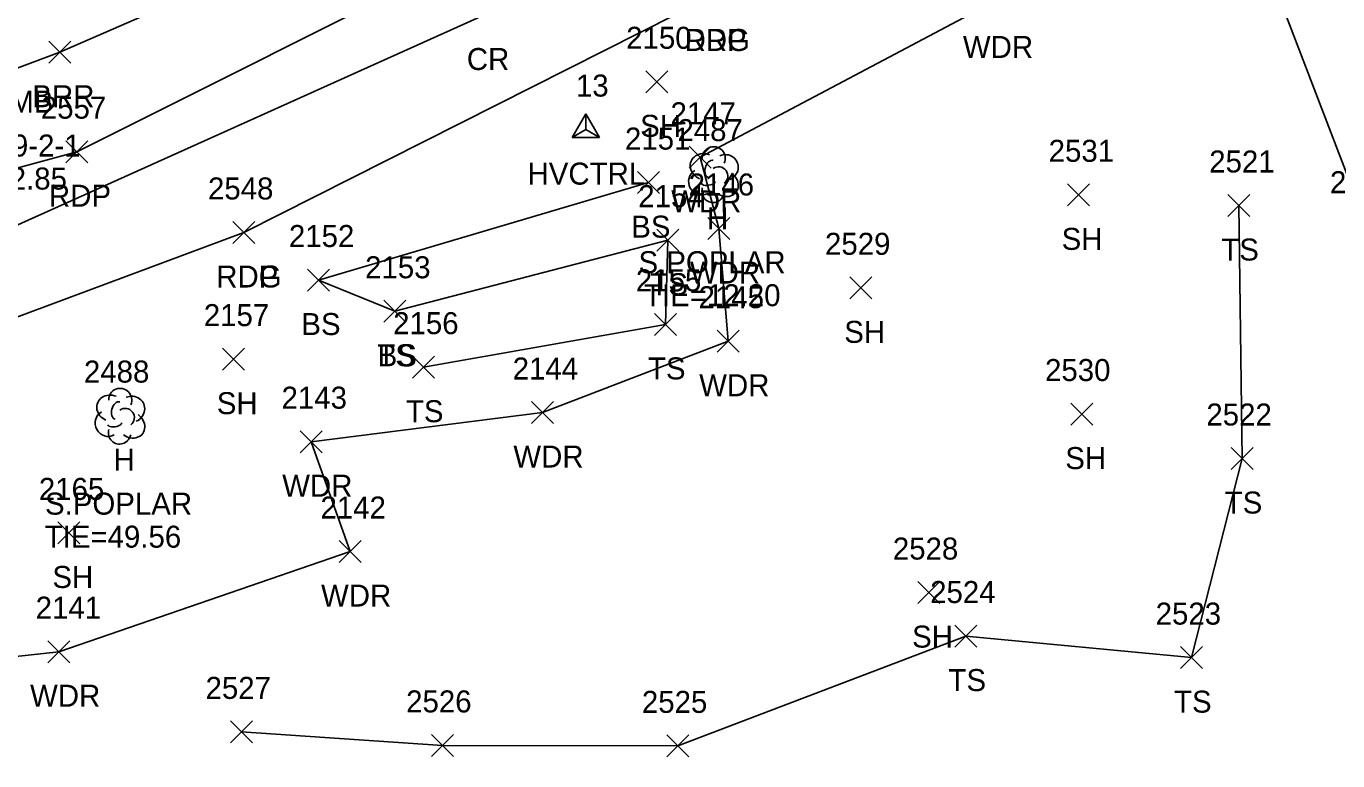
# Model space of a CAD drawing. Extents: x 1609623 to 1616187, y 756677 to 762826.
# Drawn here: x 1610303.4 to 1610422.7, y 761855.2 to 761921.9 of the extents above; entities that cross this region are included whole.
import ezdxf

# ---------------------------------------------------------------- set-up
doc = ezdxf.new("R2010")
doc.units = 0
for name, color, linetype in [('C_A', 7, 'Continuous'), ('C_I', 7, 'Continuous'), ('CPSM', 7, 'Continuous'), ('L_A', 7, 'Continuous'), ('L_C', 7, 'Continuous'), ('L_I', 7, 'Continuous'), ('L_TIC', 7, 'Continuous'), ('LABL', 7, 'Continuous'), ('LAWA', 7, 'Continuous'), ('LELB', 7, 'Continuous'), ('LTD', 7, 'Continuous'), ('P_A', 7, 'Continuous'), ('P_I', 7, 'Continuous'), ('P_TIC', 7, 'Continuous'), ('PET', 7, 'Continuous'), ('PEU', 7, 'Continuous'), ('PRC', 7, 'Continuous'), ('R_A', 7, 'Continuous'), ('U_A', 7, 'Continuous'), ('U_C', 7, 'Continuous')]:
    doc.layers.add(name, color=color, linetype=linetype)

msp = doc.modelspace()

# ---------------------------------------------------------------- linework, layer by layer
at = {"layer": 'CPSM'}
for p, q in [((1610353.04, 761911.84), (1610354.29, 761914)), ((1610355.54, 761911.84), (1610354.29, 761914)), ((1610354.29, 761912.56), (1610354.29, 761914)), ((1610353.04, 761911.84), (1610354.29, 761912.56)), ((1610353.04, 761911.84), (1610355.54, 761911.84)), ((1610354.29, 761912.56), (1610354.29, 761912.56)), ((1610354.29, 761912.56), (1610355.54, 761911.84))]:
    msp.add_line(p, q, dxfattribs=at)
at = {"layer": 'L_TIC'}
for points in [[(1610305.47, 761918.59), (1610307.47, 761920.59)], [(1610307.47, 761918.59), (1610305.47, 761920.59)], [(1610359.74, 761915.9), (1610361.74, 761917.9)], [(1610361.74, 761915.9), (1610359.74, 761917.9)], [(1610363.69, 761909.04), (1610365.69, 761911.04)], [(1610365.69, 761909.04), (1610363.69, 761911.04)], [(1610358.98, 761906.74), (1610360.98, 761908.74)], [(1610360.98, 761906.74), (1610358.98, 761908.74)], [(1610398.08, 761905.63), (1610400.08, 761907.63)], [(1610400.08, 761905.63), (1610398.08, 761907.63)], [(1610412.67, 761904.66), (1610414.67, 761906.66)], [(1610414.67, 761904.66), (1610412.67, 761906.66)], [(1610360.75, 761901.51), (1610362.75, 761903.51)], [(1610362.75, 761901.51), (1610360.75, 761903.51)], [(1610365.39, 761902.57), (1610367.39, 761904.57)], [(1610367.39, 761902.57), (1610365.39, 761904.57)], [(1610328.98, 761897.89), (1610330.98, 761899.89)], [(1610330.98, 761897.89), (1610328.98, 761899.89)], [(1610378.31, 761897.18), (1610380.31, 761899.18)], [(1610380.31, 761897.18), (1610378.31, 761899.18)], [(1610335.92, 761895.05), (1610337.92, 761897.05)], [(1610337.92, 761895.05), (1610335.92, 761897.05)], [(1610335.92, 761895.05), (1610337.92, 761897.05)], [(1610337.92, 761895.05), (1610335.92, 761897.05)], [(1610360.53, 761893.86), (1610362.53, 761895.86)], [(1610362.53, 761893.86), (1610360.53, 761895.86)], [(1610366.24, 761892.33), (1610368.24, 761894.33)], [(1610368.24, 761892.33), (1610366.24, 761894.33)], [(1610321.25, 761890.7), (1610323.25, 761892.7)], [(1610323.25, 761890.7), (1610321.25, 761892.7)], [(1610338.52, 761889.97), (1610340.52, 761891.97)], [(1610340.52, 761889.97), (1610338.52, 761891.97)], [(1610349.34, 761885.85), (1610351.34, 761887.85)], [(1610351.34, 761885.85), (1610349.34, 761887.85)], [(1610398.4, 761885.71), (1610400.4, 761887.71)], [(1610400.4, 761885.71), (1610398.4, 761887.71)], [(1610328.32, 761883.2), (1610330.32, 761885.2)], [(1610330.32, 761883.2), (1610328.32, 761885.2)], [(1610412.98, 761881.67), (1610414.98, 761883.67)], [(1610414.98, 761881.67), (1610412.98, 761883.67)], [(1610306.29, 761874.91), (1610308.29, 761876.91)], [(1610308.29, 761874.91), (1610306.29, 761876.91)], [(1610331.85, 761873.22), (1610333.85, 761875.22)], [(1610333.85, 761873.22), (1610331.85, 761875.22)], [(1610384.47, 761869.49), (1610386.47, 761871.49)], [(1610386.47, 761869.49), (1610384.47, 761871.49)], [(1610387.86, 761865.54), (1610389.86, 761867.54)], [(1610389.86, 761865.54), (1610387.86, 761867.54)], [(1610305.38, 761864.12), (1610307.38, 761866.12)], [(1610307.38, 761864.12), (1610305.38, 761866.12)], [(1610408.37, 761863.58), (1610410.37, 761865.58)], [(1610410.37, 761863.58), (1610408.37, 761865.58)], [(1610321.97, 761856.83), (1610323.97, 761858.83)], [(1610323.97, 761856.83), (1610321.97, 761858.83)], [(1610340.27, 761855.6), (1610342.27, 761857.6)], [(1610342.27, 761855.6), (1610340.27, 761857.6)], [(1610361.65, 761855.56), (1610363.65, 761857.56)], [(1610363.65, 761855.56), (1610361.65, 761857.56)]]:
    msp.add_lwpolyline(points, dxfattribs=at)
at = {"layer": 'LABL'}
msp.add_lwpolyline([(1610248.25, 761903.55), (1610212.86, 761902.85), (1610172.33, 761900.95), (1610131.44, 761903.3), (1610100.93, 761896.76), (1610074.3, 761892.77), (1610070.02, 761901.24), (1610088.05, 761924.14), (1610103.11, 761932.23), (1610130.22, 761924.96), (1610177.67, 761924.02), (1610222.12, 761925.25), (1610272.69, 761923.3), (1610298.02, 761931.54), (1610307.47, 761946.97), (1610343.23, 761952.19), (1610333.93, 761931.55), (1610306.47, 761919.59), (1610275.72, 761908.1)], dxfattribs=at)
at = {"layer": 'LAWA'}
for points in [[(1610414.2, 761932.81), (1610425.31, 761903.78)], [(1610526.97, 761857.61), (1610496.05, 761855.92), (1610466.25, 761855.65), (1610453.5, 761854.66), (1610420.91, 761848.73), (1610387.01, 761845.92), (1610353.13, 761844.36), (1610319.01, 761845.83), (1610291.04, 761846.73), (1610266.51, 761849.04), (1610263.26, 761856.4), (1610283.44, 761862.62), (1610306.38, 761865.12), (1610332.85, 761874.22), (1610329.32, 761884.2), (1610350.34, 761886.85), (1610367.24, 761893.33), (1610366.39, 761903.57), (1610364.69, 761910.04), (1610391.22, 761924.07)]]:
    msp.add_lwpolyline(points, dxfattribs=at)
at = {"layer": 'LELB'}
for points in [[(1610359.98, 761907.74), (1610329.98, 761898.89), (1610336.92, 761896.05)], [(1610413.67, 761905.66), (1610413.98, 761882.67), (1610409.37, 761864.58), (1610388.86, 761866.54), (1610362.65, 761856.56), (1610341.27, 761856.6), (1610322.97, 761857.83)], [(1610336.92, 761896.05), (1610361.75, 761902.51), (1610361.53, 761894.86), (1610339.52, 761890.97)]]:
    msp.add_lwpolyline(points, dxfattribs=at)
at = {"layer": 'LTD'}
for p, q in [((1610365.88, 761908.51), (1610365.88, 761908.51)), ((1610365.88, 761908.51), (1610365.88, 761908.51)), ((1610311.91, 761886.57), (1610311.91, 761886.57)), ((1610311.91, 761886.57), (1610311.91, 761886.57))]:
    msp.add_line(p, q, dxfattribs=at)
for centre in [(1610365.92, 761909.95), (1610311.95, 761888)]:
    msp.add_arc(centre, 1.05, 335.5272, 180.9563, dxfattribs=at)
for centre, major_axis, ratio, start_param, end_param in [((1610365.08, 761909.18), (1.21, -0.51), 0.895232, 1.570796, 4.712389), ((1610365.67, 761908.97), (-0.208, -0.792), 0.645439, 3.141593, 6.283185), ((1610366.92, 761909.1), (-1.14, -0.48), 0.949671, 1.570796, 4.712389), ((1610364.79, 761907.8), (0.58, -1.04), 0.959034, 3.141593, 6.283185), ((1610366.38, 761908.35), (-0.5, 0.667), 0.989748, 3.141593, 6.283185), ((1610366.88, 761907.68), (-1.09, 0.79), 0.841452, 1.570796, 4.712389), ((1610365.88, 761907.01), (0.26, 1.06), 0.942809, 1.570796, 4.712389), ((1610365.42, 761907.76), (-0.625, -0.083), 0.423636, 0, 3.141593), ((1610311.11, 761887.24), (1.21, -0.51), 0.895232, 1.570796, 4.712389), ((1610312.95, 761887.15), (-1.14, -0.48), 0.949671, 1.570796, 4.712389), ((1610310.82, 761885.86), (0.58, -1.04), 0.959034, 3.141593, 6.283185), ((1610311.7, 761887.03), (-0.208, -0.792), 0.645439, 3.141593, 6.283185), ((1610312.41, 761886.4), (-0.5, 0.667), 0.989748, 3.141593, 6.283185), ((1610311.45, 761885.82), (-0.625, -0.083), 0.423636, 0, 3.141593), ((1610312.91, 761885.74), (-1.09, 0.79), 0.841452, 1.570796, 4.712389), ((1610311.91, 761885.07), (0.26, 1.06), 0.942809, 1.570796, 4.712389)]:
    msp.add_ellipse(centre, major_axis=major_axis, ratio=ratio, start_param=start_param, end_param=end_param, dxfattribs=at)
at = {"layer": 'P_TIC'}
for points in [[(1610306.99, 761909.55), (1610308.99, 761911.55)], [(1610308.99, 761909.55), (1610306.99, 761911.55)], [(1610322.19, 761902.21), (1610324.19, 761904.21)], [(1610324.19, 761902.21), (1610322.19, 761904.21)], [(1610322.19, 761902.21), (1610324.19, 761904.21)], [(1610324.19, 761902.21), (1610322.19, 761904.21)]]:
    msp.add_lwpolyline(points, dxfattribs=at)
at = {"layer": 'PET'}
for points in [[(1610414.5, 761964.62), (1610377.71, 761946.31), (1610343.21, 761928.18), (1610307.99, 761910.55), (1610275.89, 761901.81)], [(1610323.19, 761903.21), (1610365.78, 761924.7)]]:
    msp.add_lwpolyline(points, dxfattribs=at)
at = {"layer": 'PEU'}
msp.add_lwpolyline([(1610246.98, 761882.07), (1610289.19, 761890.55), (1610323.19, 761903.21)], dxfattribs=at)
at = {"layer": 'PRC'}
msp.add_lwpolyline([(1610478.04, 761990.3), (1610447.54, 761976.31), (1610423.7, 761963.3), (1610382.39, 761941.65), (1610345.03, 761922.97), (1610296.28, 761901.07)], dxfattribs=at)

# ---------------------------------------------------------------- texts
at = {"layer": 'C_A'}
msp.add_text('HVCTRL', height=2, dxfattribs=at).set_placement((1610348.99, 761907.56))
at = {"layer": 'C_I'}
msp.add_text('13', height=2, dxfattribs=at).set_placement((1610353.39, 761915.56))
at = {"layer": 'L_A'}
for s, p in [('WDR', (1610388.58, 761919.07)), ('BRR', (1610303.96, 761914.59)), ('SH', (1610359.23, 761911.9)), ('WDR', (1610362.05, 761905.04)), ('BS', (1610358.42, 761902.74)), ('H', (1610365.31, 761903.51)), ('SH', (1610397.56, 761901.63)), ('TS', (1610412.08, 761900.66)), ('WDR', (1610363.75, 761898.57)), ('TS', (1610360.16, 761897.51)), ('BS', (1610328.42, 761893.89)), ('SH', (1610377.79, 761893.18)), ('TS', (1610335.33, 761891.05)), ('BS', (1610335.36, 761891.05)), ('TS', (1610359.94, 761889.86)), ('WDR', (1610364.6, 761888.33)), ('SH', (1610320.73, 761886.7)), ('TS', (1610337.93, 761885.97)), ('H', (1610311.34, 761881.57)), ('WDR', (1610347.7, 761881.85)), ('SH', (1610397.89, 761881.71)), ('WDR', (1610326.68, 761879.2)), ('TS', (1610412.39, 761877.67)), ('SH', (1610305.78, 761870.91)), ('WDR', (1610330.21, 761869.22)), ('SH', (1610383.96, 761865.49)), ('TS', (1610387.27, 761861.54)), ('WDR', (1610303.75, 761860.12)), ('TS', (1610407.78, 761859.58))]:
    msp.add_text(s, height=2, dxfattribs=at).set_placement(p)
at = {"layer": 'L_C'}
for s, p in [('S.POPLAR', (1610359.08, 761899.51)), ('TIE=12.20', (1610359.58, 761896.51)), ('S.POPLAR', (1610305.11, 761877.57)), ('TIE=49.56', (1610305.08, 761874.57))]:
    msp.add_text(s, height=2, dxfattribs=at).set_placement(p)
at = {"layer": 'L_I'}
for s, p in [('2150', (1610357.96, 761919.9)), ('2147', (1610361.99, 761913.04)), ('2487', (1610362.62, 761911.51)), ('2151', (1610357.85, 761910.74)), ('2531', (1610396.38, 761909.63)), ('2521', (1610410.98, 761908.66)), ('2146', (1610363.64, 761906.57)), ('2520', (1610421.96, 761906.78)), ('2154', (1610359.06, 761905.51)), ('2152', (1610327.29, 761901.89)), ('2529', (1610376.04, 761901.18)), ('2153', (1610334.22, 761899.05)), ('2153', (1610334.22, 761899.05)), ('2155', (1610358.84, 761897.86)), ('2145', (1610364.54, 761896.33)), ('2157', (1610319.55, 761894.7)), ('2156', (1610336.77, 761893.97)), ('2488', (1610308.65, 761889.57)), ('2144', (1610347.64, 761889.85)), ('2530', (1610396.05, 761889.71)), ('2143', (1610326.62, 761887.2)), ('2522', (1610410.72, 761885.67)), ('2165', (1610304.55, 761878.91)), ('2142', (1610330.16, 761877.22)), ('2528', (1610382.21, 761873.49)), ('2524', (1610385.6, 761869.54)), ('2141', (1610304.26, 761868.12)), ('2523', (1610406.11, 761867.58)), ('2527', (1610319.71, 761860.83)), ('2526', (1610337.95, 761859.6)), ('2525', (1610359.39, 761859.56))]:
    msp.add_text(s, height=2, dxfattribs=at).set_placement(p)
at = {"layer": 'P_A'}
for s, p in [('RDP', (1610363.27, 761919.7)), ('CR', (1610343.47, 761917.97)), ('RDP', (1610305.47, 761905.55)), ('RDG', (1610320.68, 761898.21)), ('RDP', (1610320.68, 761898.21))]:
    msp.add_text(s, height=2, dxfattribs=at).set_placement(p)
at = {"layer": 'P_I'}
for s, p in [('2557', (1610304.73, 761913.55)), ('2548', (1610319.93, 761906.21)), ('2548', (1610319.93, 761906.21))]:
    msp.add_text(s, height=2, dxfattribs=at).set_placement(p)
at = {"layer": 'R_A'}
msp.add_text('DRG', height=2, dxfattribs=at).set_placement((1610363.27, 761919.7))
at = {"layer": 'U_A'}
msp.add_text('COMB', height=2, dxfattribs=at).set_placement((1610297.85, 761914.11))
at = {"layer": 'U_C'}
for s, p in [('#24-5/7/3/19-2-1', (1610288.57, 761910.11)), ('TIE=52.85', (1610294.69, 761907.11))]:
    msp.add_text(s, height=2, dxfattribs=at).set_placement(p)

doc.saveas('drawing.dxf')
